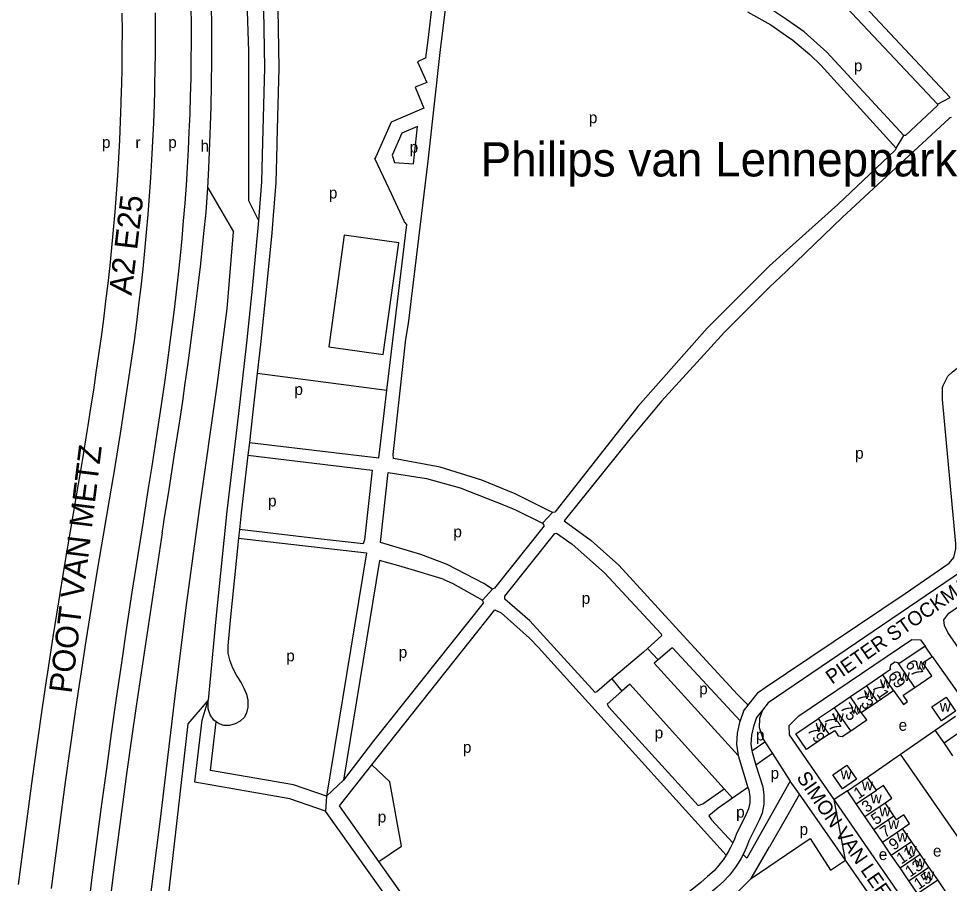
# Model space of a CAD drawing. Extents: x 157569 to 159501, y 382907 to 384670.
# Drawn here: x 157781.3 to 158107, y 383810.7 to 384113.4 of the extents above; entities that cross this region are included whole.
import ezdxf

# ---------------------------------------------------------------- set-up
doc = ezdxf.new("R2010")
doc.units = 0
for name, color, linetype in [('BLT_Basislijn', 7, 'Continuous'), ('BLT_Bebouwing', 7, 'Continuous'), ('BLT_Centroide', 7, 'Continuous'), ('BLT_Huisnummer', 7, 'Continuous'), ('BLT_Huisnummer_ tussenligend', 7, 'Continuous'), ('BLT_Onderverdeling_panden', 7, 'Continuous'), ('BLT_Sport_parknaam', 7, 'Continuous'), ('BLT_Straatnaam', 7, 'Continuous'), ('BLT_Straatnaam_hoofdweg', 7, 'Continuous'), ('BLT_Vlakafsluiter', 7, 'Continuous')]:
    doc.layers.add(name, color=color, linetype=linetype)

msp = doc.modelspace()

# ---------------------------------------------------------------- linework, layer by layer
at = {"layer": 'BLT_Basislijn'}
for p, q in [((157924.6, 384105.95), (157927.29, 384128.77)), ((157923.86, 384099.68), (157924.6, 384105.95)), ((157919.49, 384062.57), (157920.95, 384075.72)), ((157906.28, 384065.11), (157905.99, 384064.47)), ((157911.01, 384053.8), (157905.99, 384064.47)), ((157864.85, 383989.28), (157910.21, 383983.38)), ((157909.01, 383973.31), (157910.21, 383983.38)), ((157831.56, 383933.42), (157822.4, 383872.7)), ((157858.26, 383931.61), (157903.05, 383926.43)), ((157903.05, 383926.43), (157889.06, 383841.2)), ((157907.67, 383923.72), (157895.05, 383846.8)), ((157999.84, 383891.57), (157988.95, 383882.26)), ((158001.37, 383892.94), (157999.84, 383891.57)), ((158001.37, 383892.94), (158005.15, 383889)), ((158005.15, 383889), (158003.7, 383887.77)), ((158101.04, 383890.18), (158113.54, 383872.48)), ((158003.7, 383887.77), (158033.09, 383855.51)), ((157988.95, 383882.26), (157992.39, 383877.95)), ((157995.24, 383880.47), (157992.39, 383877.95)), ((157995.24, 383880.47), (158028.24, 383843.78)), ((158034.95, 383870.97), (158036.61, 383873.07)), ((158034.95, 383870.97), (158033.83, 383867.62)), ((158089.92, 383855.88), (158102.09, 383864.38)), ((158037.91, 383857.11), (158042.45, 383860.3)), ((158042.45, 383860.3), (158045.11, 383856.15)), ((158045.11, 383856.15), (158039.37, 383852.11)), ((158078.43, 383847.86), (158089.92, 383855.88)), ((158120.99, 383811.05), (158089.92, 383855.88)), ((158033.09, 383855.51), (158036.56, 383844.27)), ((157893.58, 383837.81), (157904.97, 383852.18)), ((158054.55, 383841.98), (158051.38, 383846.53)), ((158028.24, 383843.78), (158031.18, 383840.5)), ((158036.56, 383844.27), (158031.18, 383840.5)), ((158071.38, 383843.05), (158066.71, 383840.03)), ((158054.55, 383841.98), (158050, 383833.93)), ((158070.67, 383818.8), (158054.55, 383841.98)), ((157933.51, 383772.95), (157888.72, 383836.02)), ((157907.38, 383818.38), (157893.58, 383837.81)), ((158035.88, 383834.96), (158032.39, 383827.77)), ((158040.43, 383832.88), (158036.89, 383825.59)), ((158050, 383833.93), (158044.1, 383823.48)), ((158037.65, 383812.47), (158044.1, 383823.48)), ((158037.65, 383812.47), (158050, 383820.77)), ((157932.72, 383782.68), (157907.38, 383818.38)), ((158025.92, 383816.48), (158024.77, 383815.14)), ((158029.69, 383813.2), (158028.15, 383811.46))]:
    msp.add_line(p, q, dxfattribs=at)
for points in [[(157785.74, 384491.86), (157791.37, 384485.49), (157798.02, 384479.29), (157802.69, 384474.1), (157806.4, 384468.47), (157808.82, 384463.57), (157811.76, 384455.2), (157818.57, 384433.33), (157822.82, 384417.31), (157827.2, 384399.26), (157830.67, 384383.83), (157833.54, 384367.87), (157836.35, 384353.29), (157840.01, 384327.2), (157843.02, 384303.79), (157845.24, 384278.94), (157848.12, 384253.31), (157853.68, 384220.02), (157857.08, 384190.66), (157860.08, 384150.97), (157861.78, 384102.06), (157861.78, 384049.75), (157865.23, 384042.81)], [(157862.14, 384213.08), (157861.27, 384196.92), (157861.58, 384189.83), (157862.6, 384179.9), (157864.55, 384160.76), (157865.32, 384147.93), (157866.21, 384130.41), (157867.04, 384116.61), (157867.39, 384096.16), (157866.68, 384070.14), (157866.33, 384056.31), (157865.23, 384042.81)], [(157870.98, 384135.09), (157871.2, 384130.69), (157872.04, 384116.8), (157872.4, 384096.14), (157871.93, 384079.09)], [(158061.54, 384135.21), (158061.76, 384134.57), (158107.29, 384085.85)], [(158057.77, 384131.58), (158099.29, 384087.3), (158102.85, 384083.44)], [(157912.47, 383959.4), (157912.39, 383960.9), (157916.82, 384001.17), (157917.73, 384006.76), (157924.62, 384063.52), (157928.86, 384101.57), (157932.09, 384128.19)], [(158050, 384113.1), (158045.51, 384116.18), (158045.38, 384120.29), (158050, 384124.8)], [(157841.62, 384117.53), (157841.67, 384111.28), (157841.67, 384105.03), (157841.62, 384098.79), (157841.53, 384092.54), (157841.38, 384086.3), (157841.18, 384080.05), (157840.94, 384073.81), (157840.64, 384067.57), (157840.29, 384061.34), (157839.9, 384055.1), (157839.45, 384048.87), (157838.96, 384042.65), (157838.41, 384036.42), (157837.84, 384030.41), (157837.17, 384023.99), (157836.48, 384017.78), (157835.75, 384011.58), (157834.98, 384005.38), (157834.17, 383999.18), (157833.33, 383992.99), (157832.46, 383986.81), (157831.57, 383980.62), (157830.65, 383974.44), (157828.76, 383962.09), (157827.92, 383956.73), (157826.81, 383949.74), (157825, 383938.36), (157824.85, 383937.4), (157822.9, 383925.05), (157820.99, 383912.69), (157819.12, 383900.33), (157817.28, 383887.97), (157815.49, 383875.6), (157813.73, 383863.22), (157812.02, 383850.84), (157810.34, 383838.45), (157808.7, 383826.05), (157807.1, 383813.66), (157805.54, 383801.25)], [(157847.49, 384054.2), (157847.85, 384061.12), (157848.41, 384072.87), (157848.69, 384082.54), (157848.78, 384090.47), (157848.89, 384098.69), (157848.92, 384105.18), (157848.92, 384111.31), (157848.87, 384117.62)], [(157781.32, 383810.29), (157782.65, 383820.88), (157782.88, 383822.69), (157784.5, 383835.08), (157786.18, 383847.47), (157787.91, 383859.85), (157789.7, 383872.23), (157791.12, 383881.73), (157791.55, 383884.6), (157793.45, 383896.96), (157795.41, 383909.31), (157797.43, 383921.66), (157799.5, 383934), (157801.59, 383946.34), (157803.52, 383957.91), (157803.65, 383958.68), (157805.42, 383969.54), (157805.66, 383971.03), (157806.63, 383977.21), (157807.59, 383983.4), (157808.51, 383989.6), (157809.41, 383995.81), (157810.27, 384002.02), (157811.09, 384008.25), (157811.88, 384014.48), (157812.62, 384020.73), (157813.31, 384026.98), (157813.96, 384033.25), (157814.55, 384039.52), (157815.09, 384045.81), (157815.58, 384052.11), (157816.02, 384058.41), (157816.27, 384062.55), (157816.51, 384066.68), (157816.73, 384071.04), (157817.01, 384077.37), (157817.24, 384083.69), (157817.37, 384088.45), (157817.41, 384090.02), (157817.53, 384096.34), (157817.59, 384101.08), (157817.6, 384102.67), (157817.62, 384109), (157817.58, 384115.33)], [(157829.08, 384115.45), (157829.12, 384109.02), (157829.1, 384102.6), (157829.09, 384100.98), (157829.03, 384096.17), (157828.91, 384089.75), (157828.87, 384088.13), (157828.73, 384083.33), (157828.5, 384076.91), (157828.22, 384070.49), (157827.99, 384066.06), (157827.75, 384061.86), (157827.49, 384057.67), (157827.05, 384051.28), (157826.56, 384044.9), (157826.01, 384038.55), (157825.41, 384032.2), (157824.76, 384025.88), (157824.06, 384019.57), (157823.32, 384013.28), (157822.53, 384007), (157821.7, 384000.74), (157820.83, 383994.5), (157819.93, 383988.27), (157819.81, 383987.45), (157819.01, 383982.05), (157818.05, 383975.86), (157817.08, 383969.67), (157816.84, 383968.18), (157815.07, 383957.32), (157814.94, 383956.54), (157813.01, 383944.98), (157810.92, 383932.64), (157808.84, 383920.3), (157806.83, 383907.95), (157804.87, 383895.59), (157802.97, 383883.23), (157802.53, 383880.37), (157801.12, 383870.86), (157799.33, 383858.49), (157797.6, 383846.11), (157795.92, 383833.72), (157794.3, 383821.32), (157794.07, 383819.51), (157792.74, 383808.92)], [(158036.39, 384115.78), (158044.51, 384111.25), (158050, 384107.44)], [(158091.15, 384072.53), (158064.13, 384101.73), (158056.27, 384108.79), (158050, 384113.1)], [(158050, 384107.44), (158052.26, 384105.87), (158058.26, 384100.92), (158062.05, 384097.11), (158088.44, 384068.12)], [(157923.86, 384099.68), (157920.92, 384098.34), (157924.16, 384091.1), (157920.07, 384089.39), (157923.11, 384082.08), (157911.7, 384077.22), (157906.28, 384065.11)], [(158102.85, 384083.44), (158102.85, 384083.06), (158091.7, 384072.53), (158091.15, 384072.53)], [(157871.93, 384079.09), (157871.68, 384070.01), (157871.66, 384069.19)], [(158106.99, 384078.45), (158069.49, 384043.84), (158050, 384025.08)], [(158107.67, 384078.82), (158107.32, 384078.75), (158106.99, 384078.45)], [(157920.95, 384075.72), (157915.46, 384073.39), (157912.01, 384065.68)], [(157871.66, 384069.19), (157871.32, 384056.04), (157870.38, 384044.47)], [(158088.44, 384068.12), (158088.04, 384067.43), (158067.99, 384048.38), (158050, 384032.21)], [(157912.01, 384065.68), (157912.82, 384063.06), (157919.49, 384062.57)], [(157831.56, 383933.42), (157832.01, 383936.26), (157832.16, 383937.22), (157833.97, 383948.61), (157835.92, 383960.97), (157837.82, 383973.36), (157838.74, 383979.57), (157839.64, 383985.78), (157840.51, 383992), (157841.36, 383998.23), (157842.17, 384004.46), (157842.95, 384010.71), (157844.07, 384019.1), (157845.08, 384027.59), (157846.14, 384038.26), (157846.91, 384045.73), (157847.49, 384054.2)], [(157910.21, 383983.38), (157917.15, 384041.39), (157916.4, 384042.34), (157911.01, 384053.8)], [(157870.38, 384044.47), (157869.89, 384038.49), (157868.11, 384019.69), (157865.99, 383999.41), (157864.85, 383989.28)], [(157865.23, 384042.81), (157864.91, 384038.93), (157863.13, 384020.18), (157861.02, 383999.95), (157858.23, 383975.25), (157854.19, 383940.96), (157850.33, 383903.33), (157847.71, 383874.8)], [(157813.49, 383648.14), (157814.03, 383661.38), (157812.79, 383676.74), (157815.74, 383712.31), (157818.03, 383731.98), (157830.98, 383833.19), (157836.14, 383876.22), (157839.99, 383907.28), (157844.58, 383941.54), (157850.81, 383984.98), (157854.25, 384011.87), (157856.49, 384038.75)], [(158050, 384032.21), (158044.04, 384026.85), (158033.05, 384015.82)], [(158050, 384025.08), (158044.11, 384019.41), (158028.38, 384003.69), (158022.36, 383997.1)], [(158050, 383884.25), (158091.59, 383912.18), (158106.97, 383922.84), (158108.56, 383924.76), (158109.31, 383927.82), (158109.28, 383929.54), (158104.65, 383980.15), (158104.61, 383984.27), (158104.87, 383985.02), (158106.49, 383988.23), (158108.15, 383989.79), (158155.97, 384027.52)], [(158033.05, 384015.82), (158022.31, 384005.03), (157998.04, 383977.66), (157973.71, 383946.71), (157968.92, 383940.62)], [(158022.36, 383997.1), (158006.34, 383979.57), (157995.21, 383966.27), (157972.26, 383937.63)], [(157864.85, 383989.28), (157863.2, 383974.68), (157862.06, 383965)], [(157907.39, 383959.64), (157909.01, 383973.31)], [(157862.06, 383965), (157861.54, 383960.56)], [(157862.06, 383965), (157907.39, 383959.64)], [(157861.54, 383960.56), (157859.16, 383940.41), (157858.57, 383934.6)], [(157861.54, 383960.56), (157905.08, 383955.36), (157902.35, 383930.99), (157901.85, 383929.52), (157887.14, 383931.25)], [(157968.17, 383940.54), (157955.1, 383947.09), (157943.41, 383951.85), (157928.88, 383956.43), (157912.47, 383959.4)], [(157947.18, 383913.67), (157944.15, 383915.68), (157931.27, 383922.39), (157922.1, 383925.83), (157907.95, 383930.03), (157910.67, 383954.56), (157924.09, 383952.46), (157935.9, 383949.23), (157951.05, 383943.2)], [(157951.05, 383943.2), (157955.17, 383941.53), (157964.65, 383936.77)], [(157968.92, 383940.62), (157968.17, 383940.54)], [(157972.26, 383937.63), (157981.71, 383930.7), (157991.33, 383922.07), (158015.12, 383896.12)], [(157858.57, 383934.6), (157858.26, 383931.61)], [(157887.14, 383931.25), (157858.57, 383934.6)], [(157964.65, 383936.77), (157965.23, 383935.87), (157947.85, 383914.07), (157947.18, 383913.67)], [(157858.26, 383931.61), (157855.3, 383902.84), (157854.48, 383893.86), (157854.55, 383891.34), (157855.08, 383888.96), (157856.12, 383886.17), (157857.72, 383883.19), (157859.17, 383880.89), (157860.13, 383879.04), (157861.02, 383876.92), (157861.53, 383874.87), (157861.56, 383872.38), (157861.11, 383870.45), (157860.31, 383868.87), (157858.88, 383867.5), (157857.1, 383866.52), (157855.11, 383865.96), (157853.18, 383865.99), (157851.46, 383866.55), (157850.47, 383867.28)], [(157951.46, 383911.21), (157968.98, 383933.24), (157969.61, 383933.32)], [(157969.61, 383933.32), (157975.04, 383929.48), (157986.33, 383919.42), (158006.18, 383898.02), (158006.34, 383897.38), (158001.37, 383892.94)], [(158122.98, 383874.82), (158106.49, 383898.56), (158105.29, 383900.94), (158105.16, 383902.94), (158106.81, 383905.27), (158143.74, 383930.49)], [(157929.87, 383917.24), (157922.16, 383919.57), (157914.42, 383921.83), (157907.67, 383923.72)], [(158111.25, 383919.87), (158043.67, 383873.96), (158041.62, 383871.36)], [(157929.87, 383917.24), (157933.25, 383915.68), (157943.65, 383909.89)], [(157988.95, 383882.26), (157983.66, 383877.73), (157983.12, 383877.57), (157960.18, 383902.64), (157951.46, 383910.25), (157951.46, 383911.21)], [(157943.65, 383909.89), (157943.89, 383908.82), (157905.52, 383860.66), (157895.05, 383846.8)], [(157904.97, 383852.18), (157947.99, 383906.45)], [(157947.99, 383906.45), (157950.21, 383905.46), (157960.1, 383896.51), (157963.27, 383893.23), (158028.94, 383820.57)], [(158015.12, 383896.12), (158032.84, 383876.79), (158036.61, 383873.07)], [(158066.71, 383840.03), (158051.09, 383862.75), (158050.93, 383866), (158054.33, 383869.32), (158093.87, 383896.1), (158096.91, 383896), (158098.57, 383893.79)], [(158033.83, 383867.62), (158010.27, 383893.07), (158009.95, 383893.07), (158005.15, 383889)], [(158042.92, 383879.49), (158050, 383884.25)], [(158036.61, 383873.07), (158040.21, 383877.66), (158042.92, 383879.49)], [(157992.39, 383877.95), (157987.27, 383873.42), (157987.88, 383872.39), (158019.1, 383837.99), (158020.73, 383838.51), (158028.24, 383843.78)], [(157822.4, 383872.7), (157820.91, 383862.21), (157819.2, 383849.85), (157817.53, 383837.49), (157815.89, 383825.11), (157814.29, 383812.74), (157812.73, 383800.36), (157811.79, 383792.78), (157810.55, 383782.39), (157809.07, 383769.98), (157807.59, 383757.57), (157806.11, 383745.16), (157804.62, 383732.75), (157803.44, 383722.82), (157803.26, 383720.32), (157802.37, 383707.84), (157801.47, 383695.36), (157800.58, 383682.87), (157799.69, 383670.39), (157799.15, 383662.94), (157798.79, 383657.91), (157798.37, 383651.98)], [(157847.71, 383874.8), (157840.49, 383866.61), (157838.62, 383850.06)], [(157888.72, 383836.02), (157876.24, 383840.33), (157842.97, 383846.12), (157845.5, 383867.86), (157847.71, 383874.8)], [(157850.47, 383867.28), (157849.68, 383867.86), (157848.31, 383869.67), (157847.69, 383871.78), (157847.71, 383874.8)], [(158041.62, 383871.36), (158039.49, 383868.79), (158038.44, 383865.64), (158037.75, 383862.58), (158037.56, 383859.59), (158037.91, 383857.11)], [(158041.62, 383871.36), (158040.54, 383868.39), (158040.43, 383865.32), (158041.75, 383861.39), (158042.45, 383860.3)], [(157889.06, 383841.2), (157877.5, 383845.19), (157848.48, 383850.24), (157850.47, 383867.28)], [(158033.83, 383867.62), (158033.62, 383866.98), (158032.78, 383863.3), (158032.54, 383859.39), (158033.08, 383855.52), (158033.09, 383855.51)], [(158037.91, 383857.11), (158037.98, 383856.62), (158039.37, 383852.11)], [(158045.11, 383856.15), (158050, 383848.52), (158051.38, 383846.53)], [(157838.62, 383850.06), (157829.34, 383768.34), (157825.09, 383733.58)], [(157907.38, 383818.38), (157915.29, 383823.7), (157911.28, 383846.25), (157904.97, 383852.18)], [(158039.37, 383852.11), (158041.71, 383844.55), (158042.16, 383841.54), (158042.16, 383838.43), (158041.51, 383835.31), (158040.43, 383832.88)], [(158051.38, 383846.53), (158036.14, 383819.57), (158034.84, 383820.81)], [(158036.56, 383844.27), (158036.82, 383843.43), (158037.16, 383841.17), (158037.16, 383838.95), (158036.72, 383836.85), (158035.88, 383834.96)], [(158031.18, 383840.5), (158026.17, 383836.99), (158022.86, 383834.35), (158023.8, 383832.9), (158031.24, 383824.86)], [(158097.89, 383794.92), (158067.2, 383839.32), (158066.71, 383840.03)], [(158032.39, 383827.77), (158031.82, 383826.22), (158031.24, 383824.86)], [(158050, 383820.77), (158058.34, 383826.38), (158065.4, 383815.28), (158070.67, 383818.8)], [(158031.24, 383824.86), (158031.17, 383824.7), (158030.45, 383823.21), (158029.66, 383821.76), (158028.94, 383820.57)], [(158036.89, 383825.59), (158036.28, 383823.96), (158035.6, 383822.37), (158034.84, 383820.81)], [(158028.94, 383820.57), (158028.81, 383820.35), (158027.88, 383818.98), (158026.89, 383817.65), (158025.92, 383816.48)], [(158034.84, 383820.81), (158034.02, 383819.28), (158033.12, 383817.8), (158032.16, 383816.35), (158031.14, 383814.96), (158030.04, 383813.61), (158029.69, 383813.2)], [(158105.69, 383765.29), (158105.78, 383767.62), (158102.33, 383773.28), (158070.67, 383818.8)], [(158024.77, 383815.14), (158022.43, 383813.06), (158020.05, 383811.03), (158017.61, 383809.07), (158015.12, 383807.17), (158012.58, 383805.33), (158010, 383803.56), (158007.37, 383801.86), (158007.05, 383801.65)], [(158028.15, 383811.46), (158025.77, 383809.33), (158023.33, 383807.26), (158020.84, 383805.25), (158018.31, 383803.31), (158015.73, 383801.43), (158013.1, 383799.62), (158010.42, 383797.87), (158009.7, 383797.41)], [(158031.54, 383806.22), (158037.65, 383812.47)]]:
    msp.add_lwpolyline(points, dxfattribs=at)
msp.add_lwpolyline([(157895.3, 384037.59), (157889.87, 383998.54), (157908.91, 383995.89), (157914.34, 384034.95)], close=True, dxfattribs=at)
at = {"layer": 'BLT_Bebouwing'}
for p, q in [((158098.57, 383893.79), (158089.37, 383887.54)), ((158101.04, 383890.18), (158098.57, 383893.79)), ((158083.74, 383883.71), (158078.11, 383879.88)), ((158078.11, 383879.88), (158072.48, 383876.05)), ((158072.48, 383876.05), (158066.85, 383872.21)), ((158081.85, 383874.39), (158087.48, 383878.22)), ((158100.88, 383872.5), (158105.87, 383875.92)), ((158105.87, 383875.92), (158109.24, 383871)), ((158066.85, 383872.21), (158061.22, 383868.38)), ((158076.22, 383870.55), (158081.85, 383874.39)), ((158104.25, 383867.58), (158100.88, 383872.5)), ((158109.24, 383871), (158104.25, 383867.58)), ((158105.17, 383859.89), (158102.09, 383864.38)), ((158108.25, 383855.4), (158105.17, 383859.89)), ((158066.25, 383848.66), (158071.21, 383852.05)), ((158071.21, 383852.05), (158074.56, 383847.15)), ((158069.6, 383843.76), (158066.25, 383848.66)), ((158074.56, 383847.15), (158069.6, 383843.76)), ((158081.49, 383843.37), (158078.43, 383847.86)), ((158074.45, 383838.57), (158071.38, 383843.05)), ((158077.51, 383834.08), (158074.45, 383838.57)), ((158087.62, 383834.39), (158084.56, 383838.88)), ((158080.58, 383829.58), (158077.51, 383834.08)), ((158083.64, 383825.09), (158080.58, 383829.58)), ((158093.75, 383825.41), (158090.69, 383829.9)), ((158086.71, 383820.6), (158083.64, 383825.09)), ((158096.82, 383820.92), (158093.75, 383825.41)), ((158089.77, 383816.11), (158086.71, 383820.6)), ((158099.88, 383816.43), (158096.82, 383820.92)), ((158102.95, 383811.94), (158099.88, 383816.43)), ((158092.84, 383811.62), (158089.77, 383816.11)), ((158095.9, 383807.13), (158092.84, 383811.62)), ((158106.01, 383807.45), (158102.95, 383811.94))]:
    msp.add_line(p, q, dxfattribs=at)
for points in [[(158089.37, 383887.54), (158089.11, 383887.92), (158087.92, 383888.1), (158086.49, 383887.11), (158086.26, 383885.9), (158086.43, 383885.62), (158083.74, 383883.71)], [(158094.95, 383879.33), (158100.85, 383883.36), (158097.73, 383887.92), (158101.04, 383890.18)], [(158087.48, 383878.22), (158090.94, 383873.32), (158092.42, 383874.33), (158090.9, 383876.55), (158094.95, 383879.33)], [(158072.55, 383864.13), (158078.16, 383867.95), (158076.22, 383870.55)], [(158102.09, 383864.38), (158105.06, 383866.41), (158109.18, 383869.24)], [(158064.96, 383862.89), (158063.74, 383862.07), (158057.09, 383857.54), (158053.34, 383863.03), (158061.22, 383868.38)], [(158064.96, 383862.89), (158066.87, 383864.19), (158067.5, 383863.27), (158068.13, 383862.34), (158069.52, 383862.07), (158072.55, 383864.13)], [(158071.38, 383843.05), (158075.51, 383845.88), (158078.43, 383847.86)], [(158084.56, 383838.88), (158086.96, 383840.57), (158083.96, 383844.96), (158081.49, 383843.37)], [(158090.69, 383829.9), (158093.12, 383831.64), (158091.05, 383834.67), (158088.58, 383832.99), (158087.62, 383834.39)]]:
    msp.add_lwpolyline(points, dxfattribs=at)
at = {"layer": 'BLT_Onderverdeling_panden'}
for p, q in [((158094.95, 383879.33), (158089.37, 383887.54)), ((158087.48, 383878.22), (158083.74, 383883.71)), ((158081.85, 383874.39), (158078.11, 383879.88)), ((158076.22, 383870.55), (158072.48, 383876.05)), ((158072.55, 383864.13), (158066.85, 383872.21)), ((158064.96, 383862.89), (158061.22, 383868.38)), ((158105.17, 383859.89), (158112.26, 383864.75)), ((158074.45, 383838.57), (158081.49, 383843.37)), ((158077.51, 383834.08), (158084.56, 383838.88)), ((158080.58, 383829.58), (158087.62, 383834.39)), ((158083.64, 383825.09), (158090.69, 383829.9)), ((158086.71, 383820.6), (158093.75, 383825.41)), ((158089.77, 383816.11), (158096.82, 383820.92)), ((158092.84, 383811.62), (158099.88, 383816.43)), ((158095.9, 383807.13), (158102.95, 383811.94))]:
    msp.add_line(p, q, dxfattribs=at)
at = {"layer": 'BLT_Vlakafsluiter'}
for p, q in [((158102.85, 384083.44), (158107.29, 384085.85)), ((158088.44, 384068.12), (158091.15, 384072.53)), ((157847.49, 384054.2), (157856.49, 384038.75)), ((157964.65, 383936.77), (157968.17, 383940.54)), ((157943.65, 383909.89), (157947.18, 383913.67)), ((157895.05, 383846.8), (157889.06, 383841.2)), ((157889.06, 383841.2), (157888.72, 383836.02)), ((158070.67, 383818.8), (158066.71, 383840.03))]:
    msp.add_line(p, q, dxfattribs=at)

# ---------------------------------------------------------------- texts
at = {"layer": 'BLT_Centroide'}
for s, p in [('p', (158073.62, 384095.01)), ('p', (157980.87, 384076.82)), ('p', (157810.49, 384068.17)), ('r', (157822.2, 384068.09)), ('p', (157833.68, 384068.17)), ('h', (157844.96, 384066.88)), ('p', (157918.18, 384066.49)), ('p', (157889.88, 384050.48)), ('p', (157877.85, 383981.68)), ('p', (158074.06, 383959.35)), ('p', (157868.62, 383942.66)), ('p', (157933.48, 383931.85)), ('p', (157978.38, 383908.56)), ('p', (157874.98, 383888.43)), ('p', (157914.35, 383889.68)), ('w', (158095.2, 383885.48)), ('w', (158082.79, 383879.03)), ('w', (158089.36, 383881.5)), ('p', (158019.48, 383876.88)), ('w', (158077.16, 383875.22)), ('w', (158072.5, 383870.09)), ('w', (158103.68, 383870.83)), ('w', (158066.24, 383867.16)), ('w', (158060.27, 383863.72)), ('e', (158089.28, 383864.14)), ('p', (158003.93, 383861.47)), ('p', (158039.37, 383860.74)), ('p', (157936.8, 383856.41)), ('p', (158044.46, 383847.32)), ('w', (158069.02, 383847.17)), ('w', (158076.45, 383843.22)), ('w', (158079.51, 383838.72)), ('p', (158032.42, 383833.7)), ('w', (158082.57, 383834.22)), ('p', (157907.01, 383832.04)), ('w', (158085.63, 383829.75)), ('p', (158054.63, 383827.67)), ('w', (158088.7, 383825.25)), ('w', (158091.76, 383820.75)), ('e', (158101.31, 383820.1)), ('e', (158082.34, 383818.88)), ('w', (158094.83, 383816.28)), ('w', (158097.9, 383811.78))]:
    msp.add_text(s, height=4, dxfattribs=at).set_placement(p)
at = {"layer": 'BLT_Huisnummer'}
for s, rotation, p in [('67', 304.2334, (158091.47, 383887.33)), ('71', 304.2334, (158079.74, 383879.44)), ('75', 304.2334, (158068.66, 383872.15)), ('79', 304.2334, (158057.16, 383864.32)), ('1', 34.3141, (158075.25, 383840.06)), ('5', 34.3141, (158081.33, 383830.99)), ('9', 34.3141, (158087.57, 383822.07)), ('13', 34.3141, (158093.28, 383812.73))]:
    msp.add_text(s, height=4, rotation=rotation, dxfattribs=at).set_placement(p)
at = {"layer": 'BLT_Huisnummer_ tussenligend'}
for s, rotation, p in [('69', 304.2334, (158085.38, 383883.48)), ('73', 304.2334, (158074.19, 383876.11)), ('77', 304.2334, (158062.82, 383868.18)), ('3', 34.3141, (158078.06, 383835.3)), ('7', 34.3141, (158084.5, 383826.48)), ('11', 34.3141, (158090.24, 383817.26)), ('15', 34.3141, (158096.32, 383808.36))]:
    msp.add_text(s, height=4, rotation=rotation, dxfattribs=at).set_placement(p)
at = {"layer": 'BLT_Sport_parknaam'}
msp.add_text('Philips van Lenneppark', height=12, rotation=0.0131, dxfattribs=at).set_placement((157943, 384058.17))
at = {"layer": 'BLT_Straatnaam'}
for s, rotation, p in [('PIETER STOCKMANSLAAN', 34.9363, (158065.98, 383880.24)), ('SIMON VAN LEEUWENSTRAAT', 304.683, (158053.35, 383847.75))]:
    msp.add_text(s, height=5, rotation=rotation, dxfattribs=at).set_placement(p)
at = {"layer": 'BLT_Straatnaam_hoofdweg'}
for s, rotation, p in [('A2 E25', 83.1631, (157820.83, 384016.33)), ('POOT VAN METZ', 83.0229, (157799.86, 383876.99))]:
    msp.add_text(s, height=8, rotation=rotation, dxfattribs=at).set_placement(p)

doc.saveas('drawing.dxf')
